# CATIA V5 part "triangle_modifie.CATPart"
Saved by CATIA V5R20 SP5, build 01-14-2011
Part number: triangle
Bounding box of the stored display mesh (mm): x 100 to 200, y -50 to 1050, z -270 to 750
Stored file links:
  J:\projet\triangle_modifie.CATPart
  J:\projet\Product1.CATProduct
  J:\projet\bielle1.CATPart
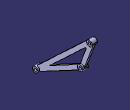
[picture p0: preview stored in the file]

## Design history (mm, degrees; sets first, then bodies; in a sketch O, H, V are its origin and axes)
Set1
  Plane1: linked copy from another document
  Line1 to Line3: linked copy from another document
  Plane2: linked copy from another document
  Plane3: linked copy from another document
  Point1 to Point3: linked copy from another document
Body1 (main body)
  Sketch1 on Plane1, origin (150, 0, 0), H (0, 1, 0), V (0, 0, 1)
    arc A1 centre (1000, 700) radius 50 from (1046.6764, 682.0748) to (965.8017, 736.4757) ccw
    point P1 (1000, 700)
    arc A2 centre (830, 220) radius 50 from (818.3442, 171.3776) to (876.3895, 238.6552) ccw
    point P2 (830, 220)
    arc A3 centre (0, -220) radius 50 from (-1.051, -170.011) to (46.7841, -237.6422) ccw
    point P3 (0, -220)
    reference projected point E1 (0, -220) from Line1
    reference projected point E2 (830, 220) from Line2
    reference projected point E3 (1000, 700) from Line3
    line L1 (46.7841, -237.6422) -> (818.3442, 171.3776)
    line L2 (783.2159, 237.6422) -> (231.3872, -54.8935)
    line L3 (805.6924, 263.6937) -> (922.2699, 592.8536)
    point P7 (805.6924, 263.6937)
    line L4 (876.3895, 238.6552) -> (1046.6764, 682.0748)
    point P8 (876.3895, 238.6552)
    line L5 (-1.051, -170.011) -> (965.8017, 736.4757)
    point P10 (-1.051, -170.011)
    construction line L6 (0, -220) -> (830, 220)
    construction line L7 (830, 220) -> (1000, 700)
    construction line L8 (1000, 700) -> (0, -220)
    arc A4 centre (830, 220) radius 50 from (805.6924, 263.6937) to (783.2159, 237.6422) ccw
    line L9 (922.2699, 592.8536) -> (231.3872, -54.8935)
    radius A1 = 50
    radius A2 = 50
    radius A3 = 50
    distance L1 L2 = 75
    distance L5 L9 = 75
    distance P10 L8 = 37.5
    distance P7 L7 = 37.5
    distance P8 L7 = 37.5
    coincidence: P3 E1, P2 E2, P1 E3, P7 A2, A2 A4
    parallelism: L3 L7, L9 L5
    symmetry: L1 L2 L6
    tangency: L5 A1, L4 A1
  Pad1: profile Sketch1, direction (1, 0, 0), length 20, mirrored extent
  Sketch2 on Plane1, origin (150, 0, 0), H (0, 1, 0), V (0, 0, 1)
    circle A1 centre (0, -220) radius 50
    circle A2 centre (830, 220) radius 50
    circle A3 centre (1000, 700) radius 50
    reference projected arc E1 centre (1000, 700) radius 50 from (1021.8954, 655.049) to (950.0981, 703.1311) ccw from edge [face of Pad1 from Sketch1.A1 | end face of Pad1]
    reference projected arc E2 centre (830, 220) radius 50 from (818.466, 171.3485) to (877.3353, 236.1048) ccw from edge [face of Pad1 from Sketch1.A2 | end face of Pad1]
    reference projected arc E3 centre (0, -220) radius 50 from (-3.1311, -170.0981) to (46.8281, -237.525) ccw from edge [face of Pad1 from Sketch1.A3 | end face of Pad1]
    coincidence: A3 E1, A2 E2, A1 E3
  Pad2: profile Sketch2, direction (1, 0, 0), up to Plane2, opposite side up to Plane3
  Sketch3 on start face of Pad2, origin (200, 1000, 700), H (0, 1, 0), V (0, 0, 1)
    point P1 (0, 0)
    reference projected point E1 (0, 0) from Point1
    coincidence: E1 P1
  Hole1: placed by Sketch3, at (200, 1000, 700) direction (-1, 0, 0), diameter 50, through (limit type 3)
  Sketch4 on start face of Pad2, origin (200, 750, 100), H (0, 1, 0), V (0, 0, 1)
    point P1 (80, 120)
    reference projected point E1 (80, 120) from Point2
    coincidence: E1 P1
  Hole2: placed by Sketch4, at (200, 830, 220) direction (-1, 0, 0), diameter 50, through (limit type 3)
  Sketch5 on start face of Pad2, origin (200, 0, -300), H (0, 1, 0), V (0, 0, 1)
    point P1 (0, 80)
    reference projected point E1 (0, 80) from Point3
    coincidence: E1 P1
  Hole3: placed by Sketch5, at (200, 0, -220) direction (-1, 0, 0), diameter 50, through (limit type 3)
  Fillet1: radius 10, on edge [face of Pad1 from Sketch1.L3 | face of Pad1 from Sketch1.L9]
  Fillet2: radius 5, on edge [face of Pad1 from Sketch1.L4 | face of Pad2 from Sketch2.A2]; edge [face of Pad2 from Sketch2.A2 | face of Pad1 from Sketch1.L3]; edge [face of Pad1 from Sketch1.L2 | face of Pad2 from Sketch2.A2]; edge [face of Pad2 from Sketch2.A2 | face of Pad1 from Sketch1.L1]; edge [face of Pad1 from Sketch1.L1 | face of Pad2 from Sketch2.A1]; edge [face of Pad2 from Sketch2.A1 | face of Pad1 from Sketch1.L5]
